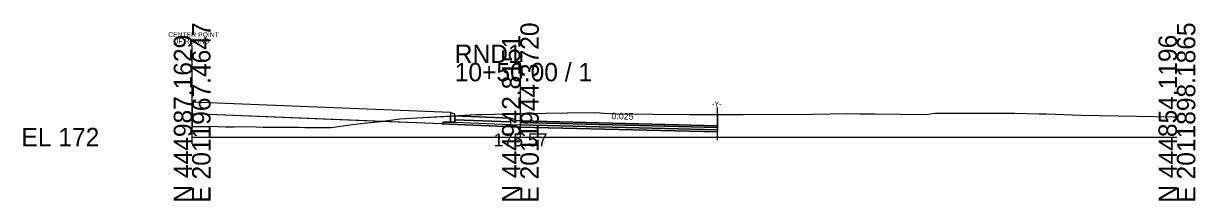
# Model space of a CAD drawing. Extents: x -26 to 153, y -10 to 6017.
# Drawn here: x -25.7 to 152.8, y 990.3 to 1017.3 of the extents above; entities that cross this region are included whole.
import ezdxf

# ---------------------------------------------------------------- set-up
doc = ezdxf.new("R2010")
doc.units = 0
for name, color, linetype in [('Exist Cross Section Cell', 7, 'Continuous'), ('Exist XS Ground Line', 7, 'Continuous'), ('Prop CMT Conc Surface', 7, 'Continuous'), ('Prop CMT Concrete Structures', 7, 'Continuous'), ('Prop CMT Pvmt Course 1', 7, 'Continuous'), ('Prop CMT Pvmt Course 1 CG', 7, 'Continuous'), ('Prop CMT Pvmt Course 2', 7, 'Continuous'), ('Prop CMT Pvmt Course 3', 7, 'Continuous'), ('Prop CMT Pvmt Surface', 7, 'Continuous'), ('Prop CMT Shear Line', 7, 'Continuous'), ('Prop CMT Shear Line Text', 7, 'Continuous'), ('Prop CMT Slope Grass', 7, 'Continuous'), ('Prop CMT Subgrade Earthwork', 7, 'Continuous'), ('Prop XS Earthwork Shape', 7, 'Continuous'), ('Prop XS SE Text', 7, 'Continuous')]:
    doc.layers.add(name, color=color, linetype=linetype)

msp = doc.modelspace()

# ---------------------------------------------------------------- linework, layer by layer
at = {"layer": 'Exist Cross Section Cell'}
for p, q in [((50, 1000), (50, 1011.31)), ((0, 1000), (50, 1000)), ((50, 1000), (150, 1000))]:
    msp.add_line(p, q, dxfattribs=at)
at = {"layer": 'Exist XS Ground Line'}
msp.add_lwpolyline([(0, 1001.62), (0.96, 1001.62), (1.87, 1001.63), (2.48, 1001.63), (2.93, 1001.64), (3.86, 1001.61), (5.16, 1001.58), (6.38, 1001.58), (7.97, 1001.59), (9.75, 1001.55), (10.82, 1001.52), (11.14, 1001.52), (11.78, 1001.53), (13, 1001.53), (13.64, 1001.53), (14.56, 1001.53), (15.04, 1001.53), (15.98, 1001.51), (16.31, 1001.5), (17.15, 1001.48), (20.72, 1001.47), (21.18, 1001.46), (25.17, 1002.04), (28.73, 1002.39), (31.63, 1002.76), (34.25, 1002.91), (43.22, 1003.44), (43.64, 1003.45), (44.17, 1003.46), (50, 1003.57), (53.85, 1003.64), (57.15, 1003.71), (61.51, 1003.77), (62.72, 1003.65), (64.64, 1003.56), (75.72, 1003.45), (79.9, 1003.44), (83.95, 1003.43), (94.54, 1003.49), (99.83, 1003.57), (101.69, 1003.55), (104.01, 1003.55), (111.81, 1003.42), (113.11, 1003.62), (125.3, 1003.63), (128.99, 1003.56), (130.16, 1003.54), (135.42, 1003.35), (149.45, 1003.07), (150, 1003.08)], dxfattribs=at)
at = {"layer": 'Prop CMT Conc Surface'}
for points in [[(40, 1003.41), (39.96, 1003.52), (39.85, 1003.56), (39.34, 1003.75)], [(40, 1003.25), (40, 1003.41)], [(50, 1002.45), (49.25, 1002.47), (49.25, 1002.64), (48.5, 1002.89)]]:
    msp.add_lwpolyline(points, dxfattribs=at)
at = {"layer": 'Prop CMT Concrete Structures'}
for points in [[(40, 1003.41), (39.96, 1003.52), (39.85, 1003.56), (39.34, 1003.75)], [(39.34, 1003.75), (39.34, 1002.25)], [(40, 1003.25), (40, 1003.41)], [(39.34, 1002.25), (40, 1002.25)], [(40, 1002.25), (40, 1003.25)], [(40, 1003.25), (40, 1002.66)], [(48.5, 1002.89), (40, 1003.23)], [(40, 1002.64), (48.5, 1002.3)], [(50, 1002.45), (49.25, 1002.47), (49.25, 1002.64), (48.5, 1002.89)], [(48.5, 1002.89), (48.5, 1001.91)], [(48.5, 1002.3), (48.5, 1002.89)], [(48.5, 1001.91), (50, 1001.87)], [(50, 1001.87), (50, 1002.45)]]:
    msp.add_lwpolyline(points, dxfattribs=at)
at = {"layer": 'Prop CMT Pvmt Course 1'}
for points in [[(50, 1002.45), (80, 1001.7)], [(50, 1002.2), (50, 1002.45)], [(80, 1001.45), (50, 1002.2)], [(80, 1001.7), (80, 1001.45)]]:
    msp.add_lwpolyline(points, dxfattribs=at)
msp.add_lwpolyline([(50, 1002.2), (50, 1002.33), (50, 1002.33), (50, 1002.2)], close=True, dxfattribs=at)
at = {"layer": 'Prop CMT Pvmt Course 1 CG'}
for points in [[(50, 1001.53), (50, 1001.87)], [(80, 1000.78), (80, 1001.11)]]:
    msp.add_lwpolyline(points, dxfattribs=at)
at = {"layer": 'Prop CMT Pvmt Course 2'}
for points in [[(50, 1001.87), (50, 1002.2)], [(50, 1002.2), (80, 1001.45)], [(80, 1001.11), (50, 1001.87)], [(80, 1001.45), (80, 1001.11)]]:
    msp.add_lwpolyline(points, dxfattribs=at)
at = {"layer": 'Prop CMT Pvmt Course 3'}
for points in [[(40, 1002.25), (48.5, 1001.91)], [(50, 1001.87), (80, 1001.11)], [(50, 1001.53), (50, 1001.87)], [(80, 1000.78), (50, 1001.53)], [(80, 1001.11), (80, 1000.78)]]:
    msp.add_lwpolyline(points, dxfattribs=at)
at = {"layer": 'Prop CMT Pvmt Surface'}
msp.add_lwpolyline([(50, 1002.45), (80, 1001.7)], dxfattribs=at)
at = {"layer": 'Prop CMT Shear Line'}
for p, q in [((0, 998.99), (0, 1013.99)), ((80, 999.52), (80, 1004.54))]:
    msp.add_line(p, q, dxfattribs=at)
at = {"layer": 'Prop CMT Slope Grass'}
for p, q in [((39.34, 1003.73), (0, 1005.3)), ((38.06, 1002.01), (0, 1003.53))]:
    msp.add_line(p, q, dxfattribs=at)
at = {"layer": 'Prop CMT Subgrade Earthwork'}
for p, q in [((0, 1005.3), (0, 1001.62)), ((80, 1000.78), (80, 1003.44)), ((38.34, 1002.29), (38.06, 1002.01))]:
    msp.add_line(p, q, dxfattribs=at)
for points in [[(38.06, 1002.01), (50, 1001.53)], [(38.34, 1002.29), (39.34, 1002.25)], [(50, 1001.53), (80, 1000.78)]]:
    msp.add_lwpolyline(points, dxfattribs=at)
at = {"layer": 'Prop XS Earthwork Shape'}
for points in [[(0, 1003.53), (0, 1001.62), (0.96, 1001.62), (1.87, 1001.63), (2.48, 1001.63), (2.93, 1001.64), (3.86, 1001.61), (5.16, 1001.58), (6.38, 1001.58), (7.97, 1001.59), (9.75, 1001.55), (10.82, 1001.52), (11.14, 1001.52), (11.78, 1001.53), (13, 1001.53), (13.64, 1001.53), (14.56, 1001.53), (15.04, 1001.53), (15.98, 1001.51), (16.31, 1001.5), (17.15, 1001.48), (20.72, 1001.47), (21.18, 1001.46), (25.17, 1002.04), (28.72, 1002.39)], [(40, 1003.25), (43.22, 1003.44), (43.64, 1003.45), (44.17, 1003.46), (50, 1003.57), (53.85, 1003.64), (57.15, 1003.71), (61.51, 1003.77), (62.72, 1003.65), (64.64, 1003.56), (75.72, 1003.45), (79.9, 1003.44), (80, 1003.44), (80, 1001.7), (50, 1002.45), (49.25, 1002.47), (49.25, 1002.64), (48.5, 1002.89), (40, 1003.23)], [(38.06, 1002.01), (28.72, 1002.39), (28.73, 1002.39), (31.63, 1002.76), (34.25, 1002.91), (39.34, 1003.21), (39.34, 1002.25), (38.34, 1002.29)], [(50, 1001.87), (50, 1002.45), (80, 1001.7), (80, 1000.78), (50, 1001.53), (38.06, 1002.01), (38.34, 1002.29), (39.34, 1002.25), (40, 1002.25), (40, 1002.64), (48.5, 1002.3), (48.5, 1001.91)], [(39.34, 1003.21), (40, 1003.25), (40, 1003.23), (40, 1002.66), (40, 1002.64), (40, 1002.25), (39.34, 1002.25)], [(40, 1002.64), (40, 1002.66), (40, 1003.23), (48.5, 1002.89), (48.5, 1002.3)], [(49.25, 1002.64), (48.5, 1002.89), (48.5, 1002.3), (48.5, 1001.91), (50, 1001.87), (50, 1002.45), (49.25, 1002.47)]]:
    msp.add_lwpolyline(points, close=True, dxfattribs=at)

# ---------------------------------------------------------------- texts
at = {"layer": 'Exist Cross Section Cell'}
for s, p in [('E 2011967.4647', (2.8, 990)), ('E 2011944.3720', (52.8, 990)), ('E 2011898.1865', (152.8, 990)), ('N 444987.1629', (0, 990)), ('N 444942.8151', (50, 990)), ('N 444854.1196', (150, 990))]:
    msp.add_text(s, height=2.8, rotation=90, dxfattribs=at).set_placement(p)
for s, p in [('RND1', (40, 1011.31)), ('10+50.00 / 1', (40, 1008.51)), ('EL 172', (-26, 998.6))]:
    msp.add_text(s, height=2.8, dxfattribs=at).set_placement(p)
at = {"layer": 'Exist XS Ground Line'}
msp.add_text('175.57', height=2, dxfattribs=at).set_placement((45.94, 998.57))
at = {"layer": 'Prop CMT Shear Line Text'}
for s, p in [('CENTER POINT', (-3.64, 1015.25)), ('OF ROUND', (-2.88, 1014.27)), ('-Y-', (79.21, 1004.65))]:
    msp.add_text(s, height=0.75, dxfattribs=at).set_placement(p)
at = {"layer": 'Prop XS SE Text'}
msp.add_text('0.025', height=1, rotation=358.5613, dxfattribs=at).set_placement((63.87, 1002.73))

doc.saveas('drawing.dxf')
